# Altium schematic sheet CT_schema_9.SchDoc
size 209 x 185 mm
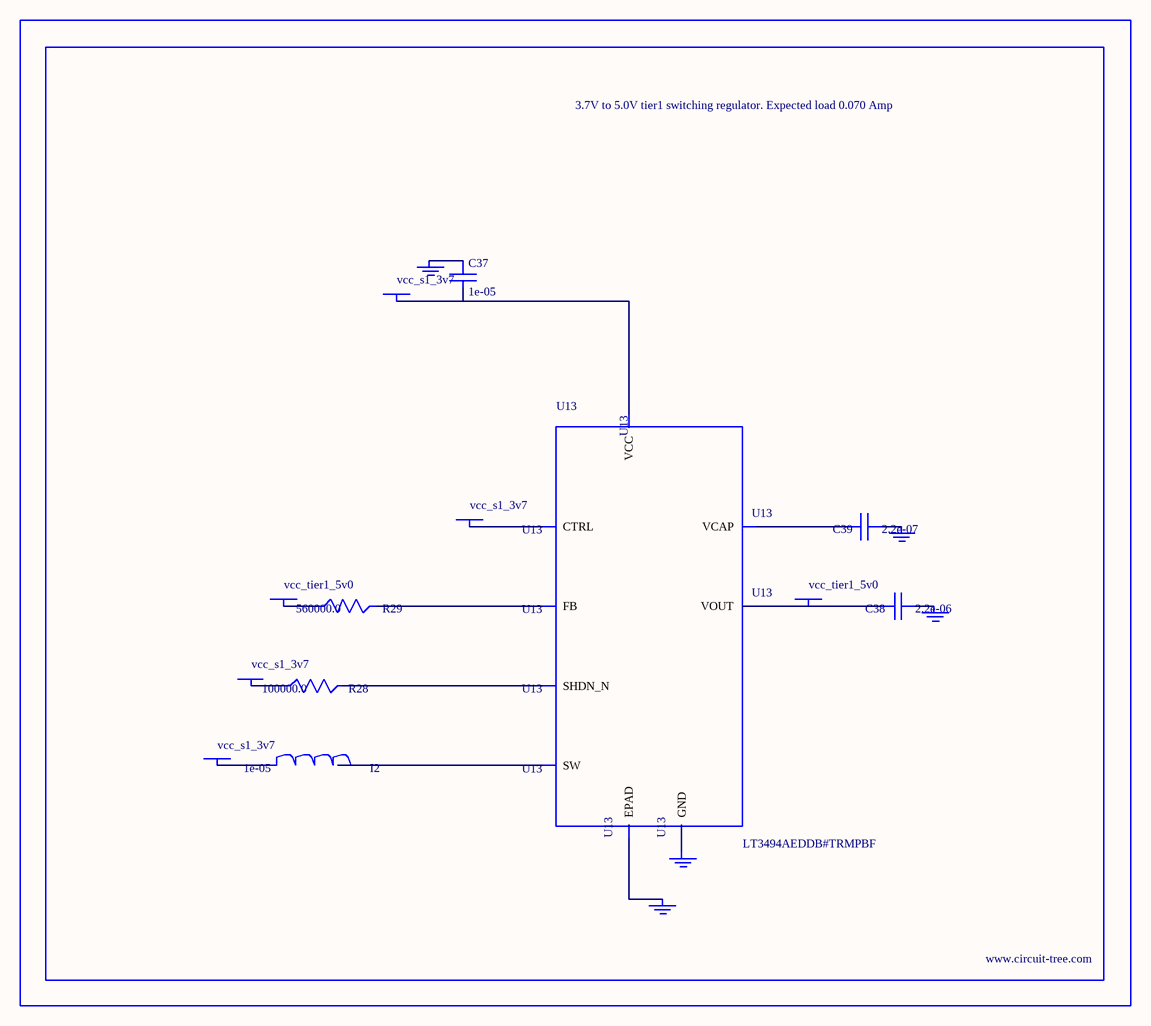
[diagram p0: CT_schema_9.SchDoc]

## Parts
BORDER8  (no value)
C37  1e-05  [C1210]
C38  2.2e-06  [C0603]
C39  2.2e-07  [C0603]
GND_INSTANCE_8_0  (no value)
GND_INSTANCE_8_1  (no value)
GND_INSTANCE_8_2  (no value)
GND_INSTANCE_8_3  (no value)
GND_INSTANCE_8_4  (no value)
I2  1e-05  [L1210]
POWER_INSTANCE_8_0  vcc_s1_3v7
POWER_INSTANCE_8_1  vcc_s1_3v7
POWER_INSTANCE_8_2  vcc_s1_3v7
POWER_INSTANCE_8_3  vcc_s1_3v7
POWER_INSTANCE_8_4  vcc_tier1_5v0
POWER_INSTANCE_8_5  vcc_tier1_5v0
R28  100000.0  [R0603]
R29  560000.0  [R0603]
U13  LT3494AEDDB#TRMPBF  [DFN-8_DDB]

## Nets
NetC37_1: C37.1 GND_INSTANCE_8_0.0(GND)
NetC37_2: C37.2 POWER_INSTANCE_8_1.0(PWR) U13.3(VCC)
NetC38_1: C38.1 GND_INSTANCE_8_1.0(GND)
NetC38_2: C38.2 POWER_INSTANCE_8_5.0(PWR) U13.7(VOUT)
NetC39_1: C39.1 GND_INSTANCE_8_2.0(GND)
NetC39_2: C39.2 U13.8(VCAP)
NetGND_INSTANCE_8_3_0: GND_INSTANCE_8_3.0(GND) U13.9(EPAD)
NetGND_INSTANCE_8_4_0: GND_INSTANCE_8_4.0(GND) U13.2(GND)
NetI2_1: I2.1 POWER_INSTANCE_8_0.0(PWR)
NetI2_2: I2.2 U13.1(SW)
NetPOWER_INSTANCE_8_2_0: POWER_INSTANCE_8_2.0(PWR) U13.4(CTRL)
NetPOWER_INSTANCE_8_3_0: POWER_INSTANCE_8_3.0(PWR) R28.1
NetPOWER_INSTANCE_8_4_0: POWER_INSTANCE_8_4.0(PWR) R29.1
NetR28_2: R28.2 U13.5(SHDN_N)
NetR29_2: R29.2 U13.6(FB)

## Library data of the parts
BORDER8 = BORDER_PAGE8
C37 = C1210C106K5PACTU
C38 = GRM188R61H225KE1115D
C39 = C0603C224K3RAC
GND_INSTANCE_8_0-GND_INSTANCE_8_4 = GND
I2 = CBC3225T100MR
POWER_INSTANCE_8_0-POWER_INSTANCE_8_5 = PWR
R28 = RC0603JR-07100KL
R29 = RC0603JR-07560KL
